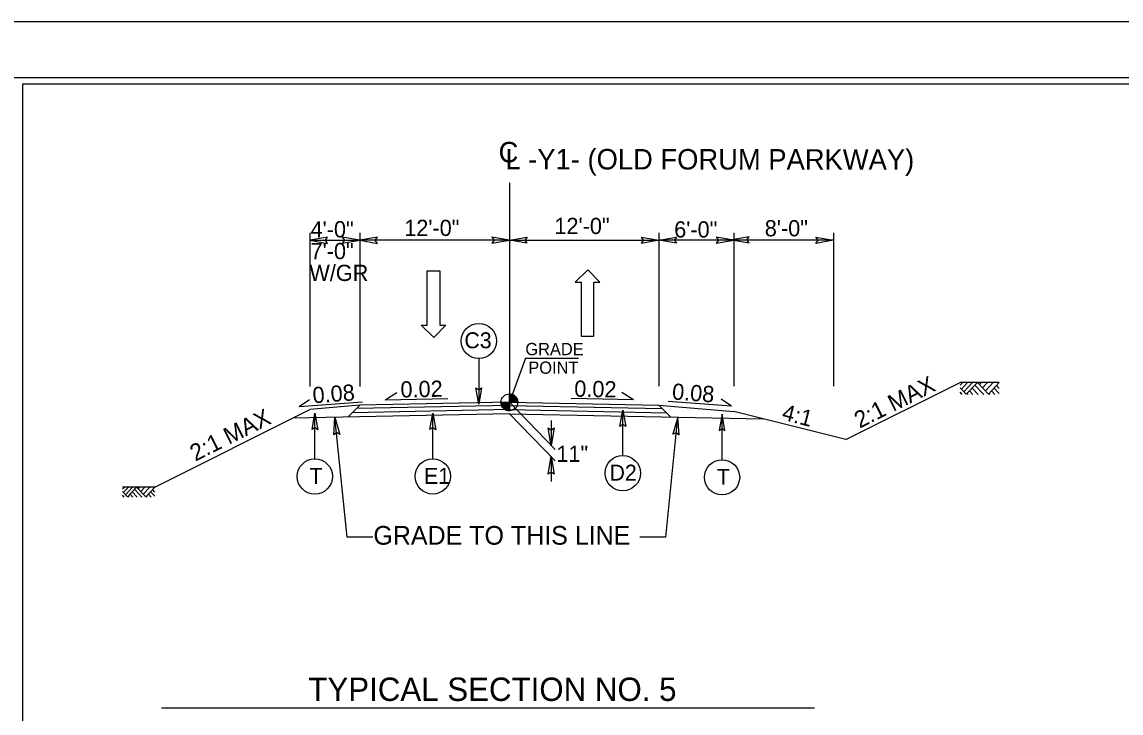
# Model space of a CAD drawing. Extents: x 1904401 to 1905163, y 193929 to 194736.
# Drawn here: x 1904744 to 1904832.2, y 194418.9 to 194474.3 of the extents above; entities that cross this region are included whole.
import ezdxf

# ---------------------------------------------------------------- set-up
doc = ezdxf.new("R2010")
doc.units = 0
for name, color, linetype in [('Old_Level_1', 7, 'Continuous'), ('Old_Level_11', 7, 'Continuous'), ('Old_Level_20', 7, 'Continuous'), ('Old_Level_3', 7, 'Continuous'), ('Prop Dimension Text', 7, 'Continuous'), ('Prop Lane Arrow CELL', 7, 'Continuous'), ('Sheet Cutting Line CELL', 7, 'Continuous'), ('Sheet Plot Border Inside CELL', 7, 'Continuous'), ('Sheet Plot Border Outside CELL', 7, 'Continuous'), ('Sheet Typical CELL', 7, 'Continuous'), ('Typical Arrow Superelevation CELL', 7, 'Continuous'), ('Typical Berm CELL', 7, 'Continuous'), ('Typical Hinge Slope Arterial CELL', 7, 'Continuous'), ('Typical Hinge Slope Interstate CELL', 7, 'Continuous'), ('Typical Terminator CELL', 7, 'Continuous'), ('Typical Text Centerline CELL', 7, 'Continuous')]:
    doc.layers.add(name, color=color, linetype=linetype)

# ---------------------------------------------------------------- blocks, each defined once
blk = doc.blocks.new('TERMINATOR')
at = {"layer": 'Typical Terminator CELL'}
blk.add_lwpolyline([(-0.469, 0.081), (0, 0), (-0.471, -0.083), (-0.411, 0)], close=True, dxfattribs=at)

msp = doc.modelspace()

# ---------------------------------------------------------------- linework, layer by layer
at = {"layer": 'Old_Level_1'}
for p, q in [((1904782.469, 194443.81), (1904783.144, 194443.81)), ((1904783.142, 194443.135), (1904783.144, 194443.81)), ((1904783.144, 194443.81), (1904783.142, 194443.135)), ((1904783.144, 194443.81), (1904783.144, 194444.485)), ((1904783.819, 194443.81), (1904783.144, 194443.81)), ((1904783.144, 194443.81), (1904786.818, 194440.014)), ((1904783.162, 194442.894), (1904786.818, 194439.117)), ((1904786.502, 194442.341), (1904786.502, 194440.341)), ((1904786.497, 194439.448), (1904786.497, 194437.448)), ((1904752.261, 194437.01), (1904752.091, 194436.827)), ((1904752.581, 194437.01), (1904752.167, 194436.566)), ((1904752.914, 194437.01), (1904752.334, 194436.387)), ((1904753.236, 194437.009), (1904752.495, 194436.213)), ((1904753.657, 194436.205), (1904753.071, 194436.833)), ((1904753.967, 194436.223), (1904753.236, 194437.009)), ((1904753.5, 194437.01), (1904753.367, 194436.867)), ((1904753.902, 194437.01), (1904753.569, 194436.651)), ((1904754.3, 194437.01), (1904753.767, 194436.437)), ((1904754.691, 194437.002), (1904753.967, 194436.223)), ((1904754.691, 194436.601), (1904754.505, 194436.801)), ((1904752.495, 194436.213), (1904752.091, 194436.648)), ((1904752.225, 194436.205), (1904752.091, 194436.348)), ((1904752.626, 194436.205), (1904752.557, 194436.279)), ((1904752.921, 194436.205), (1904752.704, 194436.438)), ((1904753.287, 194436.205), (1904752.887, 194436.634)), ((1904754.092, 194436.205), (1904754.021, 194436.281)), ((1904754.403, 194436.205), (1904754.176, 194436.448)), ((1904754.691, 194436.268), (1904754.349, 194436.634)), ((1904755.227, 194419.297), (1904807.62, 194419.297))]:
    msp.add_line(p, q, dxfattribs=at)
for points in [[(1904782.472, 194443.81), (1904782.472, 194443.737)], [(1904782.485, 194443.81), (1904782.485, 194443.657)], [(1904782.499, 194443.81), (1904782.499, 194443.609)], [(1904782.512, 194443.81), (1904782.512, 194443.569)], [(1904782.526, 194443.81), (1904782.526, 194443.537)], [(1904782.539, 194443.81), (1904782.539, 194443.509)], [(1904782.553, 194443.81), (1904782.553, 194443.483)], [(1904782.566, 194443.81), (1904782.566, 194443.459)], [(1904782.58, 194443.81), (1904782.58, 194443.438)], [(1904782.593, 194443.81), (1904782.593, 194443.419)], [(1904782.607, 194443.81), (1904782.607, 194443.401)], [(1904782.62, 194443.81), (1904782.62, 194443.384)], [(1904782.634, 194443.81), (1904782.634, 194443.368)], [(1904782.647, 194443.81), (1904782.647, 194443.353)], [(1904782.661, 194443.81), (1904782.661, 194443.338)], [(1904782.674, 194443.81), (1904782.674, 194443.324)], [(1904782.688, 194443.81), (1904782.688, 194443.312)], [(1904782.701, 194443.81), (1904782.701, 194443.3)], [(1904782.715, 194443.81), (1904782.715, 194443.288)], [(1904782.728, 194443.81), (1904782.728, 194443.278)], [(1904782.742, 194443.81), (1904782.742, 194443.267)], [(1904782.755, 194443.81), (1904782.755, 194443.258)], [(1904782.769, 194443.81), (1904782.769, 194443.249)], [(1904782.782, 194443.81), (1904782.782, 194443.24)], [(1904782.796, 194443.81), (1904782.796, 194443.231)], [(1904782.809, 194443.81), (1904782.809, 194443.224)], [(1904782.823, 194443.81), (1904782.823, 194443.216)], [(1904782.836, 194443.81), (1904782.836, 194443.209)], [(1904782.85, 194443.81), (1904782.85, 194443.203)], [(1904782.863, 194443.81), (1904782.863, 194443.197)], [(1904782.877, 194443.81), (1904782.877, 194443.191)], [(1904782.89, 194443.81), (1904782.89, 194443.185)], [(1904782.904, 194443.81), (1904782.904, 194443.179)], [(1904782.917, 194443.81), (1904782.917, 194443.174)], [(1904782.931, 194443.81), (1904782.931, 194443.17)], [(1904782.944, 194443.81), (1904782.944, 194443.165)], [(1904782.958, 194443.81), (1904782.958, 194443.162)], [(1904782.971, 194443.81), (1904782.971, 194443.158)], [(1904782.985, 194443.81), (1904782.985, 194443.155)], [(1904782.998, 194443.81), (1904782.998, 194443.152)], [(1904783.012, 194443.81), (1904783.012, 194443.149)], [(1904783.025, 194443.81), (1904783.025, 194443.146)], [(1904783.039, 194443.81), (1904783.039, 194443.144)], [(1904783.052, 194443.81), (1904783.052, 194443.141)], [(1904783.066, 194443.81), (1904783.066, 194443.14)], [(1904783.079, 194443.81), (1904783.079, 194443.138)], [(1904783.093, 194443.81), (1904783.093, 194443.137)], [(1904783.106, 194443.81), (1904783.106, 194443.137)], [(1904783.12, 194443.81), (1904783.12, 194443.135)], [(1904783.133, 194443.81), (1904783.133, 194443.135), (1904783.133, 194443.135)], [(1904783.15, 194444.485), (1904783.15, 194444.485), (1904783.15, 194443.81)], [(1904783.163, 194444.485), (1904783.163, 194443.81)], [(1904783.177, 194444.484), (1904783.177, 194443.81)], [(1904783.19, 194444.484), (1904783.19, 194443.81)], [(1904783.204, 194444.482), (1904783.204, 194443.81)], [(1904783.217, 194444.481), (1904783.217, 194443.81)], [(1904783.231, 194444.479), (1904783.231, 194443.81)], [(1904783.244, 194444.478), (1904783.244, 194443.81)], [(1904783.258, 194444.476), (1904783.258, 194443.81)], [(1904783.271, 194444.473), (1904783.271, 194443.81)], [(1904783.285, 194444.47), (1904783.285, 194443.81)], [(1904783.298, 194444.467), (1904783.298, 194443.81)], [(1904783.312, 194444.464), (1904783.312, 194443.81)], [(1904783.325, 194444.46), (1904783.325, 194443.81)], [(1904783.339, 194444.457), (1904783.339, 194443.81)], [(1904783.352, 194444.452), (1904783.352, 194443.81)], [(1904783.366, 194444.448), (1904783.366, 194443.81)], [(1904783.379, 194444.443), (1904783.379, 194443.81)], [(1904783.393, 194444.437), (1904783.393, 194443.81)], [(1904783.406, 194444.431), (1904783.406, 194443.81)], [(1904783.42, 194444.425), (1904783.42, 194443.81)], [(1904783.433, 194444.419), (1904783.433, 194443.81)], [(1904783.447, 194444.413), (1904783.447, 194443.81)], [(1904783.46, 194444.406), (1904783.46, 194443.81)], [(1904783.474, 194444.398), (1904783.474, 194443.81)], [(1904783.487, 194444.391), (1904783.487, 194443.81)], [(1904783.501, 194444.383), (1904783.501, 194443.81)], [(1904783.514, 194444.374), (1904783.514, 194443.81)], [(1904783.528, 194444.365), (1904783.528, 194443.81)], [(1904783.541, 194444.355), (1904783.541, 194443.81)], [(1904783.555, 194444.346), (1904783.555, 194443.81)], [(1904783.568, 194444.335), (1904783.568, 194443.81)], [(1904783.582, 194444.323), (1904783.582, 194443.81)], [(1904783.595, 194444.311), (1904783.595, 194443.81)], [(1904783.609, 194444.299), (1904783.609, 194443.81)], [(1904783.622, 194444.286), (1904783.622, 194443.81)], [(1904783.636, 194444.272), (1904783.636, 194443.81)], [(1904783.649, 194444.257), (1904783.649, 194443.81)], [(1904783.663, 194444.241), (1904783.663, 194443.81)], [(1904783.676, 194444.224), (1904783.676, 194443.81)], [(1904783.69, 194444.206), (1904783.69, 194443.81)], [(1904783.703, 194444.187), (1904783.703, 194443.81)], [(1904783.717, 194444.166), (1904783.717, 194443.81)], [(1904783.73, 194444.143), (1904783.73, 194443.81)], [(1904783.744, 194444.119), (1904783.744, 194443.81)], [(1904783.757, 194444.091), (1904783.757, 194443.81)], [(1904783.771, 194444.059), (1904783.771, 194443.81)], [(1904783.784, 194444.022), (1904783.784, 194443.81)], [(1904783.798, 194443.975), (1904783.798, 194443.81)], [(1904783.811, 194443.906), (1904783.811, 194443.81)], [(1904754.691, 194437.01), (1904752.091, 194437.01)]]:
    msp.add_lwpolyline(points, dxfattribs=at)
msp.add_circle((1904783.143, 194443.81), 0.675, dxfattribs=at)
for start, end in [(179.99048, 269.99048), (359.99048, 89.99048)]:
    msp.add_arc((1904783.143, 194443.81), 0.675, start, end, dxfattribs=at)
at = {"layer": 'Old_Level_11'}
for p, q in [((1904780.689, 194447.318), (1904780.689, 194443.664)), ((1904767.533, 194439.272), (1904767.533, 194442.926)), ((1904776.996, 194439.275), (1904776.996, 194442.929)), ((1904792.24, 194439.536), (1904792.24, 194443.19)), ((1904800.204, 194439.201), (1904800.204, 194442.856))]:
    msp.add_line(p, q, dxfattribs=at)
for points in [[(1904780.914, 194444.973), (1904780.689, 194443.664), (1904780.455, 194444.98), (1904780.689, 194444.813)], [(1904767.308, 194441.617), (1904767.533, 194442.926), (1904767.767, 194441.61), (1904767.533, 194441.777)], [(1904776.771, 194441.62), (1904776.996, 194442.929), (1904777.229, 194441.613), (1904776.996, 194441.78)], [(1904792.015, 194441.881), (1904792.24, 194443.19), (1904792.473, 194441.874), (1904792.24, 194442.041)], [(1904800.429, 194441.546), (1904800.204, 194442.856), (1904799.971, 194441.54), (1904800.204, 194441.707)]]:
    msp.add_lwpolyline(points, close=True, dxfattribs=at)
for centre in [(1904780.689, 194448.733), (1904792.24, 194438.122), (1904767.533, 194437.857), (1904776.996, 194437.861), (1904800.204, 194437.787)]:
    msp.add_circle(centre, 1.414, dxfattribs=at)
at = {"layer": 'Old_Level_3'}
for q in [(1904783.144, 194443.81), (1904788.691, 194447.353)]:
    msp.add_line((1904784.433, 194447.353), q, dxfattribs=at)
at = {"layer": 'Prop Lane Arrow CELL'}
for p, q in [((1904771.144, 194457.416), (1904771.144, 194445.082)), ((1904795.144, 194457.416), (1904795.144, 194445.104)), ((1904767.144, 194456.816), (1904771.144, 194456.816)), ((1904783.144, 194456.816), (1904771.144, 194456.816)), ((1904783.144, 194456.816), (1904795.144, 194456.816)), ((1904809.144, 194456.816), (1904795.144, 194456.816)), ((1904789.424, 194454.444), (1904788.428, 194453.464)), ((1904790.389, 194453.464), (1904789.424, 194454.444)), ((1904776.538, 194454.35), (1904777.565, 194454.35)), ((1904776.538, 194449.992), (1904776.538, 194454.35)), ((1904777.565, 194454.35), (1904777.565, 194449.992)), ((1904788.428, 194453.464), (1904788.895, 194453.464)), ((1904788.895, 194453.464), (1904788.895, 194449.106)), ((1904789.922, 194449.106), (1904789.922, 194453.464)), ((1904789.922, 194453.464), (1904790.389, 194453.464)), ((1904777.067, 194449.012), (1904776.071, 194449.992)), ((1904776.071, 194449.992), (1904776.538, 194449.992)), ((1904778.032, 194449.992), (1904777.067, 194449.012)), ((1904777.565, 194449.992), (1904778.032, 194449.992)), ((1904788.895, 194449.106), (1904789.922, 194449.106)), ((1904819.52, 194445.406), (1904819.316, 194445.186)), ((1904819.801, 194444.45), (1904819.316, 194444.972)), ((1904819.904, 194445.406), (1904819.407, 194444.873)), ((1904820.304, 194445.406), (1904819.607, 194444.659)), ((1904820.69, 194445.405), (1904819.801, 194444.45)), ((1904820.312, 194444.44), (1904820.052, 194444.72)), ((1904820.751, 194444.44), (1904820.271, 194444.955)), ((1904821.195, 194444.44), (1904820.492, 194445.194)), ((1904821.567, 194444.462), (1904820.69, 194445.405)), ((1904821.007, 194445.406), (1904820.847, 194445.235)), ((1904821.489, 194445.406), (1904821.09, 194444.975)), ((1904821.967, 194445.406), (1904821.327, 194444.718)), ((1904822.436, 194445.396), (1904821.567, 194444.462)), ((1904822.09, 194444.44), (1904821.818, 194444.732)), ((1904822.436, 194444.516), (1904822.026, 194444.955)), ((1904822.436, 194444.915), (1904822.213, 194445.155)), ((1904783.144, 194443.81), (1904771.144, 194443.57)), ((1904783.144, 194443.81), (1904795.144, 194443.57)), ((1904819.477, 194444.44), (1904819.316, 194444.612)), ((1904819.958, 194444.44), (1904819.875, 194444.529)), ((1904821.717, 194444.44), (1904821.632, 194444.531)), ((1904771.144, 194443.57), (1904767.144, 194443.237)), ((1904770.208, 194442.635), (1904771.144, 194443.57)), ((1904783.144, 194443.227), (1904770.549, 194442.975)), ((1904783.144, 194443.56), (1904770.889, 194443.315)), ((1904783.144, 194443.56), (1904795.399, 194443.315)), ((1904783.144, 194443.227), (1904795.739, 194442.975)), ((1904796.079, 194442.635), (1904795.144, 194443.57)), ((1904795.144, 194443.57), (1904801.144, 194443.07)), ((1904783.144, 194442.893), (1904765.762, 194442.546)), ((1904770.116, 194432.99), (1904769.143, 194442.613)), ((1904783.144, 194442.893), (1904803.478, 194442.487)), ((1904795.694, 194432.99), (1904796.669, 194442.623)), ((1904772.195, 194432.99), (1904770.116, 194432.99)), ((1904795.694, 194432.99), (1904793.615, 194432.99))]:
    msp.add_line(p, q, dxfattribs=at)
msp.add_lwpolyline([(1904822.436, 194445.406), (1904819.316, 194445.406)], dxfattribs=at)
at = {"layer": 'Sheet Cutting Line CELL'}
msp.add_line((1905047.492, 194474.335), (1904710.692, 194474.335), dxfattribs=at)
at = {"layer": 'Sheet Plot Border Inside CELL'}
msp.add_lwpolyline([(1905046.592, 194469.845), (1904713.292, 194469.845), (1904713.292, 194258.825), (1905046.592, 194258.825)], close=True, dxfattribs=at)
at = {"layer": 'Sheet Plot Border Outside CELL'}
msp.add_lwpolyline([(1905047.492, 194474.335), (1904710.692, 194474.335), (1904710.692, 194254.335), (1905047.492, 194254.335)], close=True, dxfattribs=at)
at = {"layer": 'Sheet Typical CELL'}
msp.add_lwpolyline([(1905044.092, 194469.335), (1904744.092, 194469.335), (1904744.092, 194259.335), (1905044.092, 194259.335)], close=True, dxfattribs=at)
at = {"layer": 'Typical Arrow Superelevation CELL'}
for p, q in [((1904766.266, 194443.462), (1904767.093, 194444.024)), ((1904766.266, 194443.462), (1904771.347, 194443.835)), ((1904773.181, 194444.019), (1904774.121, 194444.587)), ((1904773.181, 194444.019), (1904778.192, 194444.12)), ((1904793.107, 194444.019), (1904788.096, 194444.12)), ((1904793.107, 194444.019), (1904792.167, 194444.587)), ((1904800.957, 194443.509), (1904795.877, 194443.882)), ((1904800.957, 194443.509), (1904800.13, 194444.071))]:
    msp.add_line(p, q, dxfattribs=at)
at = {"layer": 'Typical Berm CELL'}
for p, q in [((1904767.144, 194457.416), (1904767.144, 194445.082)), ((1904801.144, 194457.416), (1904801.144, 194445.104)), ((1904809.144, 194457.416), (1904809.144, 194445.104))]:
    msp.add_line(p, q, dxfattribs=at)
at = {"layer": 'Typical Hinge Slope Arterial CELL'}
for p, q in [((1904810.144, 194440.82), (1904819.316, 194445.406)), ((1904754.691, 194437.01), (1904767.144, 194443.237))]:
    msp.add_line(p, q, dxfattribs=at)
at = {"layer": 'Typical Hinge Slope Interstate CELL'}
msp.add_line((1904810.144, 194440.82), (1904801.144, 194443.07), dxfattribs=at)
at = {"layer": 'Typical Terminator CELL'}
for points in [[(1904768.55, 194457.058), (1904767.144, 194456.816), (1904768.558, 194456.566), (1904768.378, 194456.816)], [(1904769.738, 194456.574), (1904771.144, 194456.816), (1904769.73, 194457.066), (1904769.91, 194456.816)], [(1904772.55, 194457.058), (1904771.144, 194456.816), (1904772.558, 194456.566), (1904772.378, 194456.816)], [(1904781.738, 194456.574), (1904783.144, 194456.816), (1904781.73, 194457.066), (1904781.91, 194456.816)], [(1904784.55, 194456.574), (1904783.144, 194456.816), (1904784.558, 194457.066), (1904784.378, 194456.816)], [(1904793.738, 194457.058), (1904795.144, 194456.816), (1904793.73, 194456.566), (1904793.91, 194456.816)], [(1904796.55, 194456.574), (1904795.144, 194456.816), (1904796.558, 194457.066), (1904796.378, 194456.816)], [(1904799.738, 194456.574), (1904801.144, 194456.816), (1904799.73, 194457.066), (1904799.91, 194456.816)], [(1904802.376, 194457.089), (1904800.97, 194456.847), (1904802.383, 194456.597), (1904802.204, 194456.847)], [(1904807.738, 194457.058), (1904809.144, 194456.816), (1904807.73, 194456.566), (1904807.91, 194456.816)], [(1904769.056, 194441.189), (1904769.143, 194442.613), (1904769.546, 194441.235), (1904769.278, 194441.386)], [(1904796.756, 194441.199), (1904796.669, 194442.623), (1904796.266, 194441.245), (1904796.534, 194441.396)]]:
    msp.add_lwpolyline(points, close=True, dxfattribs=at)
at = {"layer": 'Typical Text Centerline CELL'}
msp.add_line((1904783.144, 194461.416), (1904783.144, 194443.81), dxfattribs=at)

# ---------------------------------------------------------------- block references
at = {"layer": 'Old_Level_1', "xscale": 3, "yscale": 3}
for p, rotation in [((1904786.502, 194440.341), -90), ((1904786.497, 194439.448), 90)]:
    msp.add_blockref('TERMINATOR', p, dxfattribs=dict(at, rotation=rotation))

# ---------------------------------------------------------------- texts
at = {"layer": 'Old_Level_1'}
for s, p in [('4\'-0" ', (1904767.189, 194457.047)), ('6\'-0"', (1904796.363, 194457.034)), ('7\'-0"', (1904767.189, 194455.297)), ('W/GR', (1904767.095, 194453.547))]:
    msp.add_text(s, height=1.3, dxfattribs=at).set_placement(p)
at = {"layer": 'Old_Level_11'}
for s, p in [('GRADE', (1904784.424, 194447.59)), ('POINT', (1904784.661, 194446.099))]:
    msp.add_text(s, height=0.984, dxfattribs=at).set_placement(p)
at = {"layer": 'Old_Level_20'}
for s, height, p in [('C3', 1.2792, (1904779.531, 194448.147)), ('11"', 1.3, (1904786.913, 194439.025)), ('T', 1.279, (1904767.097, 194437.26)), ('E1', 1.2792, (1904776.288, 194437.264)), ('D2', 1.2792, (1904791.175, 194437.525)), ('T', 1.279, (1904799.776, 194437.19))]:
    msp.add_text(s, height=height, dxfattribs=at).set_placement(p)
at = {"layer": 'Prop Dimension Text'}
for rotation, p in [(1.1462, (1904774.417, 194444.192)), (358.8538, (1904788.338, 194444.263))]:
    msp.add_text('0.02', height=1.3, rotation=rotation, dxfattribs=at).set_placement(p)
at = {"layer": 'Prop Lane Arrow CELL'}
for s, height, p in [('12\'-0"', 1.3, (1904774.704, 194457.159)), ('12\'-0"', 1.3, (1904786.754, 194457.316)), ('8\'-0"', 1.3, (1904803.632, 194457.131)), ('TYPICAL SECTION NO. 5', 1.875, (1904767.012, 194419.841))]:
    msp.add_text(s, height=height, dxfattribs=at).set_placement(p)
for s, height, rotation, p in [('0.08', 1.3, 4.19823, (1904767.399, 194443.725)), ('0.08', 1.3, 355.80177, (1904796.162, 194444.041)), ('GRADE TO THIS LINE', 1.5, 0.00016, (1904772.231, 194432.383))]:
    msp.add_text(s, height=height, rotation=rotation, dxfattribs=at).set_placement(p)
at = {"layer": 'Typical Hinge Slope Arterial CELL'}
for p in [(1904811.24, 194441.686), (1904757.945, 194439.042)]:
    msp.add_text('2:1 MAX', height=1.35, rotation=26.56505, dxfattribs=at).set_placement(p)
at = {"layer": 'Typical Hinge Slope Interstate CELL'}
msp.add_text('4:1', height=1.3, rotation=345.52839, dxfattribs=at).set_placement((1904804.932, 194442.435))
at = {"layer": 'Typical Text Centerline CELL'}
msp.add_text('C', height=1.64, dxfattribs=at).set_placement((1904782.276, 194463.068))
msp.add_text('L -Y1- (OLD FORUM PARKWAY) ', height=1.64109, rotation=359.9469, dxfattribs=at).set_placement((1904782.821, 194462.508))

doc.saveas('drawing.dxf')
